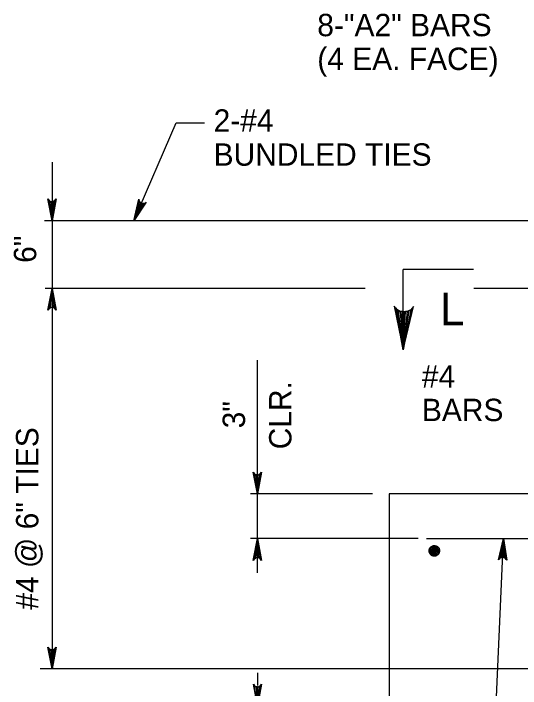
# Model space of a CAD drawing. Extents: x 3351 to 8430, y -3586 to 1457.
# Drawn here: x 4363.2 to 4432.8, y -2153.7 to -2061.1 of the extents above; entities that cross this region are included whole.
import ezdxf

# ---------------------------------------------------------------- set-up
doc = ezdxf.new("R2010")
doc.units = 0
doc.layers.add('1', color=7, linetype='Continuous')

msp = doc.modelspace()

# ---------------------------------------------------------------- linework, layer by layer
at = {"layer": '1'}
for p, q in [((4379.738, -2089.513), (4385.507, -2076.057)), ((4385.507, -2076.057), (4389.416, -2076.057)), ((4368.493, -2081.495), (4368.493, -2098.815)), ((4440.277, -2089.513), (4367.453, -2089.513)), ((4426.341, -2096.233), (4416.692, -2096.233)), ((4416.692, -2107.235), (4416.692, -2096.233)), ((4411.449, -2098.815), (4367.537, -2098.815)), ((4368.493, -2098.815), (4368.493, -2151.039)), ((4454.359, -2098.815), (4426.353, -2098.815)), ((4396.663, -2127.017), (4396.663, -2108.646)), ((4412.443, -2127.017), (4395.721, -2127.017)), ((4396.663, -2137.859), (4396.663, -2127.017)), ((4455.271, -2127.017), (4414.771, -2127.017)), ((4414.771, -2127.017), (4414.771, -2163.017)), ((4418.739, -2133.165), (4395.721, -2133.165)), ((4419.885, -2133.165), (4535.651, -2133.165)), ((4453.869, -2151.039), (4366.877, -2151.039)), ((4396.681, -2151.602), (4396.681, -2153.315))]:
    msp.add_line(p, q, dxfattribs=at)
for points in [[(4368.493, -2089.513), (4367.934, -2086.53), (4368.093, -2086.76), (4368.293, -2086.878), (4368.493, -2086.913), (4368.693, -2086.878), (4368.893, -2086.76), (4369.052, -2086.53), (4368.493, -2089.513), (4368.893, -2086.76), (4368.693, -2086.878), (4368.493, -2089.513), (4368.493, -2086.913), (4368.293, -2086.878), (4368.493, -2089.513), (4368.093, -2086.76)], [(4379.738, -2089.513), (4380.399, -2086.551), (4380.455, -2086.825), (4380.592, -2087.013), (4380.762, -2087.123), (4380.96, -2087.17), (4381.19, -2087.14), (4381.427, -2086.992), (4379.738, -2089.513), (4381.19, -2087.14), (4380.96, -2087.17), (4379.738, -2089.513), (4380.762, -2087.123), (4380.592, -2087.013), (4379.738, -2089.513), (4380.455, -2086.825)], [(4368.493, -2098.815), (4369.052, -2101.797), (4368.893, -2101.568), (4368.693, -2101.449), (4368.493, -2101.415), (4368.293, -2101.449), (4368.093, -2101.568), (4367.934, -2101.797), (4368.493, -2098.815), (4368.093, -2101.568), (4368.293, -2101.449), (4368.493, -2098.815), (4368.493, -2101.415), (4368.693, -2101.449), (4368.493, -2098.815), (4368.893, -2101.568)], [(4416.692, -2107.235), (4418.11, -2101.282), (4417.916, -2101.51), (4417.722, -2101.738), (4417.48, -2101.854), (4417.239, -2101.971), (4416.999, -2102.003), (4416.758, -2102.035), (4416.519, -2101.999), (4416.279, -2101.962), (4416.04, -2101.841), (4415.802, -2101.721), (4415.614, -2101.489), (4415.426, -2101.258), (4416.692, -2107.235), (4415.614, -2101.489), (4415.802, -2101.721), (4416.692, -2107.235), (4416.04, -2101.841), (4416.279, -2101.962), (4416.692, -2107.235), (4416.519, -2101.999), (4416.758, -2102.035), (4416.692, -2107.235), (4416.999, -2102.003), (4417.239, -2101.971), (4416.692, -2107.235), (4417.48, -2101.854), (4417.722, -2101.738), (4416.692, -2107.235), (4417.916, -2101.51)], [(4396.663, -2127.017), (4396.104, -2124.034), (4396.263, -2124.264), (4396.463, -2124.382), (4396.663, -2124.417), (4396.863, -2124.382), (4397.063, -2124.264), (4397.222, -2124.034), (4396.663, -2127.017), (4397.063, -2124.264), (4396.863, -2124.382), (4396.663, -2127.017), (4396.663, -2124.417), (4396.463, -2124.382), (4396.663, -2127.017), (4396.263, -2124.264)], [(4396.663, -2133.165), (4397.222, -2136.147), (4397.063, -2135.918), (4396.863, -2135.799), (4396.663, -2135.765), (4396.463, -2135.799), (4396.263, -2135.918), (4396.104, -2136.147), (4396.663, -2133.165), (4396.263, -2135.918), (4396.463, -2135.799), (4396.663, -2133.165), (4396.663, -2135.765), (4396.863, -2135.799), (4396.663, -2133.165), (4397.063, -2135.918)], [(4432.305, -2173.532), (4428.656, -2173.532), (4430.453, -2133.131)], [(4430.453, -2133.131), (4430.879, -2136.135), (4430.805, -2136.017), (4430.73, -2135.899), (4430.633, -2135.835), (4430.536, -2135.771), (4430.437, -2135.75), (4430.337, -2135.728), (4430.237, -2135.741), (4430.136, -2135.754), (4430.034, -2135.808), (4429.931, -2135.863), (4429.846, -2135.974), (4429.762, -2136.086), (4430.453, -2133.131), (4429.846, -2135.974), (4429.931, -2135.863), (4430.453, -2133.131), (4430.034, -2135.808), (4430.136, -2135.754), (4430.453, -2133.131), (4430.237, -2135.741), (4430.337, -2135.728), (4430.453, -2133.131), (4430.437, -2135.75), (4430.536, -2135.771), (4430.453, -2133.131), (4430.633, -2135.835), (4430.73, -2135.899), (4430.453, -2133.131), (4430.805, -2136.017)], [(4368.493, -2151.039), (4367.934, -2148.056), (4368.093, -2148.286), (4368.293, -2148.404), (4368.493, -2148.439), (4368.693, -2148.404), (4368.893, -2148.286), (4369.052, -2148.056), (4368.493, -2151.039), (4368.893, -2148.286), (4368.693, -2148.404), (4368.493, -2151.039), (4368.493, -2148.439), (4368.293, -2148.404), (4368.493, -2151.039), (4368.093, -2148.286)], [(4396.681, -2156.121), (4396.122, -2153.139), (4396.281, -2153.369), (4396.481, -2153.487), (4396.681, -2153.521), (4396.881, -2153.487), (4397.081, -2153.369), (4397.24, -2153.139), (4396.681, -2156.121), (4397.081, -2153.369), (4396.881, -2153.487), (4396.681, -2156.121), (4396.681, -2153.521), (4396.481, -2153.487), (4396.681, -2156.121), (4396.281, -2153.369)]]:
    msp.add_lwpolyline(points, dxfattribs=at)
msp.add_spline([(4420.945, -2134.847), (4420.911, -2134.919), (4420.855, -2134.911), (4420.845, -2134.797), (4420.943, -2134.735), (4421.065, -2134.797), (4421.059, -2134.911), (4420.991, -2134.979), (4420.855, -2134.991), (4420.759, -2134.919), (4420.711, -2134.803), (4420.781, -2134.645), (4420.931, -2134.613), (4421.101, -2134.663), (4421.187, -2134.767), (4421.179, -2134.945), (4421.093, -2135.061), (4420.943, -2135.103), (4420.807, -2135.073), (4420.699, -2135.007), (4420.653, -2134.891), (4420.625, -2134.741), (4420.655, -2134.601), (4420.789, -2134.513), (4420.987, -2134.473), (4421.207, -2134.561), (4421.313, -2134.715), (4421.313, -2134.919), (4421.243, -2135.093), (4421.093, -2135.211), (4420.855, -2135.223), (4420.685, -2135.131), (4420.581, -2134.967), (4420.519, -2134.797), (4420.551, -2134.589), (4420.685, -2134.447), (4420.883, -2134.363), (4421.193, -2134.413), (4421.391, -2134.585), (4421.435, -2134.825), (4421.391, -2135.061), (4421.259, -2135.245), (4421.075, -2135.319), (4420.789, -2135.311), (4420.563, -2135.183), (4420.455, -2134.991), (4420.425, -2134.785), (4420.445, -2134.613), (4420.517, -2134.423), (4420.699, -2134.291), (4420.999, -2134.247), (4421.267, -2134.325), (4421.463, -2134.505), (4421.543, -2134.725), (4421.525, -2134.999), (4421.435, -2135.257), (4421.287, -2135.367), (4421.023, -2135.463), (4420.747, -2135.421), (4420.551, -2135.333), (4420.405, -2135.163), (4420.327, -2134.987), (4420.327, -2134.797), (4420.335, -2134.589), (4420.383, -2134.399), (4420.481, -2134.291), (4420.631, -2134.197), (4420.781, -2134.139), (4420.931, -2134.119), (4421.123, -2134.145), (4421.313, -2134.207), (4421.479, -2134.329), (4421.591, -2134.485), (4421.647, -2134.681), (4421.675, -2134.863), (4421.633, -2135.073), (4421.557, -2135.245), (4421.419, -2135.399), (4421.259, -2135.503), (4421.093, -2135.567), (4420.901, -2135.573), (4420.671, -2135.519), (4420.481, -2135.399), (4420.365, -2135.277), (4420.269, -2135.119), (4420.233, -2134.959), (4420.229, -2134.767), (4420.269, -2134.561), (4420.327, -2134.467), (4420.455, -2134.329)], degree=3, dxfattribs=at)

# ---------------------------------------------------------------- texts
for s, height, p in [('8-"A2" BARS', 3.072, (4404.887, -2064.188)), ('(4 EA. FACE)', 3.072, (4404.887, -2068.826)), ('2-#4', 3.072, (4390.667, -2077.297)), ('BUNDLED TIES', 3.072, (4390.667, -2081.969)), ('L', 4.477, (4421.731, -2103.871)), ('#4', 3.072, (4419.238, -2112.422)), ('BARS', 3.072, (4419.238, -2117.03))]:
    msp.add_text(s, height=height, dxfattribs=at).set_placement(p)
for s, p in [('6"', (4366.326, -2095.303)), ('CLR.', (4401.347, -2120.899)), ('3"', (4394.973, -2118.023)), ('#4 @ 6" TIES', (4366.619, -2142.912))]:
    msp.add_text(s, height=3.072, rotation=90, dxfattribs=at).set_placement(p)

doc.saveas('drawing.dxf')
